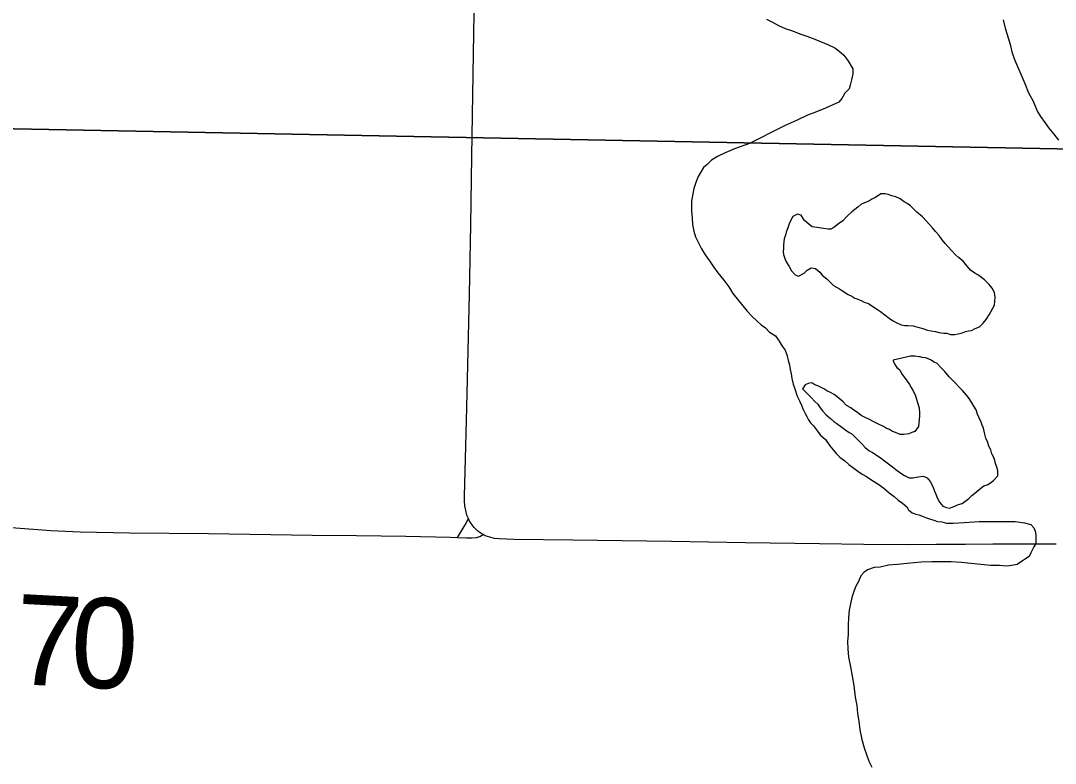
# Model space of a CAD drawing. Extents: x 2.4 to 73.1, y 4.5 to 25.6.
# Drawn here: x 33.5763 to 33.9025, y 18.8747 to 19.1088 of the extents above; entities that cross this region are included whole.
import ezdxf

# ---------------------------------------------------------------- set-up
doc = ezdxf.new("R2010")
doc.units = 0
for name, color, linetype in [('GM_X_County_Road', 7, 'Continuous'), ('GM_X_Major_River', 7, 'Continuous'), ('GM_X_Section', 7, 'Continuous'), ('GM_X_Township_Road', 7, 'Continuous'), ('GM_X_Township_Road_Text', 7, 'Continuous')]:
    doc.layers.add(name, color=color, linetype=linetype)

msp = doc.modelspace()

# ---------------------------------------------------------------- linework, layer by layer
at = {"layer": 'GM_X_County_Road'}
for points in [[(33.71741, 18.95187), (33.71697, 18.95291), (33.71656, 18.95435), (33.7163, 18.95584), (33.71617, 18.95735), (33.71613, 18.95889), (33.71637, 18.96664), (33.71687, 18.98685), (33.71779, 19.02259), (33.71815, 19.04435), (33.71853, 19.06611), (33.71919, 19.11119)], [(33.7221, 18.94676), (33.72143, 18.94712), (33.72023, 18.94799), (33.71919, 18.94904), (33.71829, 18.95023), (33.7177, 18.95125), (33.71741, 18.95187)], [(33.90268, 18.94379), (33.89395, 18.94374), (33.88277, 18.94369), (33.87419, 18.94364), (33.86494, 18.94359), (33.85606, 18.94355), (33.84208, 18.94365), (33.8281, 18.94382), (33.8048, 18.94414), (33.78148, 18.94453), (33.75039, 18.94496), (33.73173, 18.94523), (33.7271, 18.94539), (33.7256, 18.94557), (33.72414, 18.9459), (33.72274, 18.94641), (33.7221, 18.94676)]]:
    msp.add_lwpolyline(points, dxfattribs=at)
at = {"layer": 'GM_X_Major_River'}
for points in [[(33.81142, 19.10922), (33.81333, 19.10826), (33.81522, 19.10731), (33.81731, 19.10635), (33.81959, 19.10558)], [(33.90357, 19.07112), (33.90205, 19.07303), (33.90053, 19.07493), (33.89921, 19.07665), (33.89788, 19.07855), (33.89674, 19.08045), (33.89561, 19.08331), (33.89409, 19.08597), (33.89296, 19.08883), (33.88974, 19.09644), (33.88898, 19.09853), (33.88842, 19.10082), (33.88766, 19.10329), (33.8869, 19.10595), (33.88615, 19.109)], [(33.81959, 19.10558), (33.82187, 19.10463), (33.82415, 19.10386), (33.82662, 19.1029), (33.83099, 19.10118), (33.83289, 19.10022), (33.83422, 19.09927), (33.83574, 19.09793), (33.83707, 19.09622), (33.83802, 19.0947), (33.83858, 19.09355), (33.83858, 19.09203), (33.8382, 19.09013), (33.83781, 19.08842), (33.83743, 19.08729), (33.8361, 19.08596), (33.83514, 19.08425), (33.83419, 19.08311), (33.83, 19.08123), (33.82715, 19.08009), (33.8243, 19.07896), (33.82106, 19.07745), (33.81725, 19.07575), (33.81307, 19.07367), (33.80945, 19.07179), (33.80603, 19.07008), (33.80127, 19.06839), (33.79841, 19.06707), (33.79594, 19.06593), (33.79404, 19.0648), (33.7927, 19.06347), (33.79156, 19.06253), (33.7908, 19.0612), (33.78984, 19.05968), (33.78908, 19.05778), (33.78851, 19.05588), (33.78812, 19.05417), (33.78774, 19.0519), (33.78773, 19.04885), (33.78792, 19.04657), (33.7881, 19.04448), (33.78848, 19.04239), (33.78905, 19.04068), (33.78999, 19.03877), (33.79094, 19.03687), (33.79208, 19.03497), (33.7934, 19.03306), (33.79473, 19.03116), (33.79606, 19.02925), (33.79796, 19.02697), (33.79947, 19.02487), (33.8008, 19.02278), (33.80535, 19.01725), (33.80687, 19.01554), (33.80839, 19.0142), (33.80972, 19.01287), (33.81105, 19.01191), (33.81237, 19.01058), (33.81427, 19.00943), (33.81541, 19.00772), (33.81636, 19.0062), (33.81731, 19.00486), (33.81787, 19.00315), (33.81825, 19.00163), (33.81863, 19.0003), (33.81882, 18.99878), (33.81919, 18.99745), (33.81938, 18.99592), (33.81976, 18.99421), (33.82033, 18.99269), (33.82108, 18.99041), (33.82184, 18.98889), (33.82241, 18.98755), (33.82297, 18.98622), (33.82354, 18.98489), (33.82411, 18.98394), (33.82468, 18.98299), (33.82525, 18.98203), (33.8262, 18.98108), (33.82715, 18.97975), (33.82828, 18.97822), (33.82999, 18.9767), (33.83132, 18.97479), (33.83246, 18.97346), (33.83341, 18.97232), (33.83454, 18.97117), (33.83606, 18.97003), (33.83739, 18.96888), (33.83891, 18.96774), (33.84024, 18.96678), (33.84157, 18.96583), (33.8429, 18.96506), (33.84461, 18.96392), (33.84651, 18.96277), (33.84841, 18.96144), (33.85011, 18.95991), (33.85163, 18.95877), (33.85296, 18.95762), (33.85429, 18.95667), (33.85562, 18.95552), (33.85619, 18.95457)], [(33.8558, 19.05112), (33.85485, 19.05169), (33.85353, 19.05265), (33.8522, 19.05322), (33.85087, 19.05361), (33.84973, 19.05399), (33.84878, 19.05418), (33.84744, 19.05419), (33.84573, 19.05305), (33.84459, 19.05248), (33.84364, 19.05192), (33.84231, 19.05135), (33.84116, 19.05078), (33.84021, 19.05003), (33.83831, 19.04851), (33.83678, 19.04719), (33.83545, 19.04567), (33.83412, 19.04472), (33.83259, 19.04359), (33.83164, 19.04302), (33.83088, 19.04302)], [(33.83088, 19.04302), (33.82575, 19.0438), (33.8248, 19.04456), (33.82328, 19.0459), (33.82233, 19.04742), (33.82119, 19.0478), (33.81967, 19.04705), (33.8191, 19.04591), (33.81852, 19.04477), (33.81814, 19.04344), (33.81757, 19.04211), (33.81738, 19.04116), (33.817, 19.04002), (33.8168, 19.03812), (33.8168, 19.03698), (33.81661, 19.03603), (33.8168, 19.03508), (33.81717, 19.03375), (33.81755, 19.0328), (33.8185, 19.03128), (33.81926, 19.02994), (33.82039, 19.02861), (33.82153, 19.02823), (33.82325, 19.02917), (33.8242, 19.03012), (33.82553, 19.03088), (33.82686, 19.03068), (33.82819, 19.02954), (33.82895, 19.02858), (33.83047, 19.02744), (33.83142, 19.0263), (33.83256, 19.02534), (33.83446, 19.0242), (33.83541, 19.02362), (33.83712, 19.02248), (33.83825, 19.0219), (33.8392, 19.02133), (33.84016, 19.02095), (33.84129, 19.02056), (33.84224, 19.01999), (33.84357, 19.01961), (33.84528, 19.01846), (33.84642, 19.0177), (33.84737, 19.01713), (33.85003, 19.01503), (33.85117, 19.01426), (33.8525, 19.0135), (33.85383, 19.01293), (33.85497, 19.01273), (33.85592, 19.01273), (33.85763, 19.01253), (33.85915, 19.01215), (33.86067, 19.01176), (33.86219, 19.01119), (33.86333, 19.011), (33.86466, 19.0108), (33.8658, 19.01042), (33.86732, 19.01022), (33.86827, 19.01022), (33.86941, 19.00984), (33.87074, 19.00983), (33.8717, 19.01002), (33.87322, 19.0104), (33.87417, 19.01077), (33.87512, 19.01096), (33.87607, 19.01115), (33.87721, 19.01171), (33.87855, 19.01228), (33.87969, 19.01342), (33.88064, 19.01456), (33.8816, 19.01607), (33.88217, 19.01702), (33.88274, 19.01816), (33.88331, 19.01911), (33.88351, 19.02158), (33.88332, 19.0231), (33.88256, 19.02443), (33.88161, 19.02557), (33.8801, 19.0271), (33.87915, 19.02786), (33.87801, 19.02863), (33.87706, 19.0292), (33.87573, 19.03015), (33.87421, 19.03187), (33.87345, 19.03301), (33.87193, 19.03416), (33.87098, 19.03492), (33.86985, 19.03625), (33.86852, 19.03759), (33.86776, 19.03854), (33.86681, 19.03968), (33.86586, 19.04102), (33.86472, 19.04235), (33.86378, 19.04349), (33.86264, 19.04464), (33.86188, 19.04559), (33.86055, 19.04692), (33.85884, 19.04845), (33.85789, 19.0494), (33.85675, 19.05036), (33.8558, 19.05112)], [(33.83363, 18.99018), (33.83268, 18.99094), (33.83154, 18.99152), (33.8304, 18.99209), (33.82945, 18.99266), (33.82755, 18.99362), (33.8266, 18.994), (33.82565, 18.99457), (33.82451, 18.99439), (33.82356, 18.99401), (33.8228, 18.99268), (33.82413, 18.99135), (33.82545, 18.99001), (33.82659, 18.98868), (33.82754, 18.98792), (33.8283, 18.98677), (33.82906, 18.98582), (33.8302, 18.98449), (33.83153, 18.98334), (33.83266, 18.98239), (33.83361, 18.98182), (33.83513, 18.98067), (33.83646, 18.97972), (33.83741, 18.97895), (33.83836, 18.97838), (33.83931, 18.97743), (33.84026, 18.97648), (33.8414, 18.97552), (33.84254, 18.97419), (33.84367, 18.97323), (33.84481, 18.97266), (33.84633, 18.97171), (33.84766, 18.97075), (33.84861, 18.96999), (33.85108, 18.96808), (33.85222, 18.96732), (33.85374, 18.96617), (33.85488, 18.96541), (33.8564, 18.96464), (33.85754, 18.96464), (33.85925, 18.96502), (33.86077, 18.9652), (33.8621, 18.96463), (33.86305, 18.96348), (33.86381, 18.96196), (33.86437, 18.96044), (33.86475, 18.95949), (33.86532, 18.95816), (33.86589, 18.95701), (33.86703, 18.95568), (33.86817, 18.9553), (33.86912, 18.9551), (33.87026, 18.95548), (33.87197, 18.95624), (33.87311, 18.95661), (33.87521, 18.95813), (33.87616, 18.95907), (33.87711, 18.95983), (33.87845, 18.96097), (33.87997, 18.9621), (33.88092, 18.96248), (33.88206, 18.96305), (33.88301, 18.9638), (33.88435, 18.96532), (33.88435, 18.96684), (33.88397, 18.96798), (33.8836, 18.96912), (33.88341, 18.97007), (33.88303, 18.97103), (33.88246, 18.97217), (33.88208, 18.9735), (33.88151, 18.97464), (33.88114, 18.97578), (33.88057, 18.97711), (33.88019, 18.97845), (33.87982, 18.98035), (33.87944, 18.9813), (33.87906, 18.98225), (33.87849, 18.98358), (33.87792, 18.98472), (33.87754, 18.98606), (33.87678, 18.9872), (33.87603, 18.98853), (33.87527, 18.98967), (33.87451, 18.99063), (33.87318, 18.99215), (33.87204, 18.9933), (33.8711, 18.99444), (33.87015, 18.99539), (33.86901, 18.99654), (33.86749, 18.99825), (33.86635, 18.99939), (33.86521, 19.00073), (33.86426, 19.00111), (33.86312, 19.00187), (33.8616, 19.00245), (33.86046, 19.00264), (33.85983, 19.00277)], [(33.85133, 19.00172), (33.85133, 19.00153), (33.8519, 19.00039), (33.85247, 18.99943), (33.85342, 18.99867), (33.85399, 18.99753), (33.85475, 18.99639), (33.85551, 18.99544), (33.85645, 18.9941), (33.85702, 18.99315), (33.85778, 18.99182), (33.85835, 18.99049), (33.85892, 18.98877), (33.85948, 18.98668), (33.85967, 18.98516), (33.85967, 18.98421), (33.85948, 18.98307), (33.85928, 18.98079), (33.85814, 18.97927), (33.85719, 18.9789), (33.85623, 18.97852), (33.85471, 18.97833), (33.85357, 18.97834), (33.85205, 18.97891), (33.8511, 18.97929), (33.85015, 18.97987), (33.8492, 18.98025), (33.84825, 18.98082), (33.84673, 18.98159), (33.8454, 18.98216), (33.84369, 18.98312), (33.84255, 18.98369), (33.84122, 18.98427), (33.84008, 18.98522), (33.83895, 18.98598), (33.838, 18.98675), (33.83667, 18.98751), (33.83553, 18.98865), (33.83363, 18.99018)], [(33.85983, 19.00277), (33.85951, 19.00284), (33.85818, 19.00303), (33.85685, 19.00303), (33.85133, 19.00172)], [(33.85619, 18.95457), (33.85733, 18.95362), (33.85847, 18.95323), (33.85942, 18.95304), (33.86075, 18.95247), (33.86189, 18.95208), (33.86284, 18.9517), (33.86417, 18.95132), (33.86531, 18.95093), (33.86664, 18.95074), (33.86816, 18.95035), (33.87025, 18.95035), (33.87367, 18.95053), (33.87843, 18.95089), (33.88546, 18.95087), (33.88983, 18.95086), (33.89269, 18.95047), (33.89478, 18.94989), (33.89573, 18.94894), (33.8961, 18.9478), (33.89629, 18.94666), (33.89629, 18.94552), (33.89629, 18.944), (33.89571, 18.94286), (33.89476, 18.94096), (33.89419, 18.93982), (33.89304, 18.93907), (33.89209, 18.9385), (33.89038, 18.93736), (33.88867, 18.93699), (33.88715, 18.9368), (33.88486, 18.937), (33.88201, 18.93701), (33.87289, 18.93799), (33.86966, 18.93819), (33.86661, 18.9382), (33.86357, 18.9382), (33.86015, 18.93802), (33.85577, 18.93766), (33.85273, 18.93729), (33.84988, 18.93711), (33.84722, 18.93654), (33.84532, 18.93636), (33.84322, 18.93561), (33.84208, 18.93485), (33.84113, 18.93371), (33.84036, 18.932), (33.8396, 18.93049), (33.83903, 18.92916), (33.83826, 18.92688), (33.83788, 18.92498), (33.83749, 18.92289), (33.8373, 18.92061), (33.8371, 18.91814), (33.8371, 18.91529), (33.8369, 18.91301), (33.83709, 18.91073), (33.83728, 18.90807), (33.83784, 18.90502), (33.83841, 18.90217), (33.83897, 18.89913), (33.83934, 18.89552), (33.83991, 18.89285), (33.84009, 18.89038), (33.84047, 18.88791), (33.84084, 18.88525), (33.84141, 18.8822), (33.84216, 18.87954), (33.84292, 18.87745), (33.84368, 18.87536), (33.84462, 18.87345)]]:
    msp.add_lwpolyline(points, dxfattribs=at)
at = {"layer": 'GM_X_Section'}
for points in [[(33.98098, 19.57169), (33.9688, 19.06715), (33.48089, 19.0765), (33.49557, 19.58326)], [(33.9688, 19.06715), (33.95589, 18.56338), (33.46684, 18.57275), (33.48089, 19.0765)]]:
    msp.add_lwpolyline(points, close=True, dxfattribs=at)
at = {"layer": 'GM_X_Township_Road'}
for points in [[(33.48976, 18.95731), (33.49441, 18.95681), (33.50523, 18.95565), (33.51761, 18.95441), (33.53308, 18.95286), (33.55785, 18.95047), (33.57334, 18.94904), (33.58574, 18.94806), (33.59506, 18.94762), (33.61061, 18.94727), (33.63549, 18.94711), (33.66815, 18.94662), (33.68215, 18.94646), (33.6977, 18.94625), (33.71168, 18.94591), (33.71395, 18.94582)], [(33.71395, 18.94582), (33.71515, 18.94778), (33.71576, 18.94878), (33.71634, 18.94986), (33.71741, 18.95187)], [(33.71395, 18.94582), (33.71683, 18.9457), (33.71852, 18.94572), (33.71994, 18.94585), (33.72105, 18.94617), (33.7221, 18.94676)]]:
    msp.add_lwpolyline(points, dxfattribs=at)

# ---------------------------------------------------------------- texts
at = {"layer": 'GM_X_Township_Road_Text'}
for s, rotation, p in [('7', 356.9997, (33.57378, 18.89971)), ('0', 357.6046, (33.59158, 18.89878))]:
    msp.add_text(s, height=0.02841, rotation=rotation, dxfattribs=at).set_placement(p)

doc.saveas('drawing.dxf')
